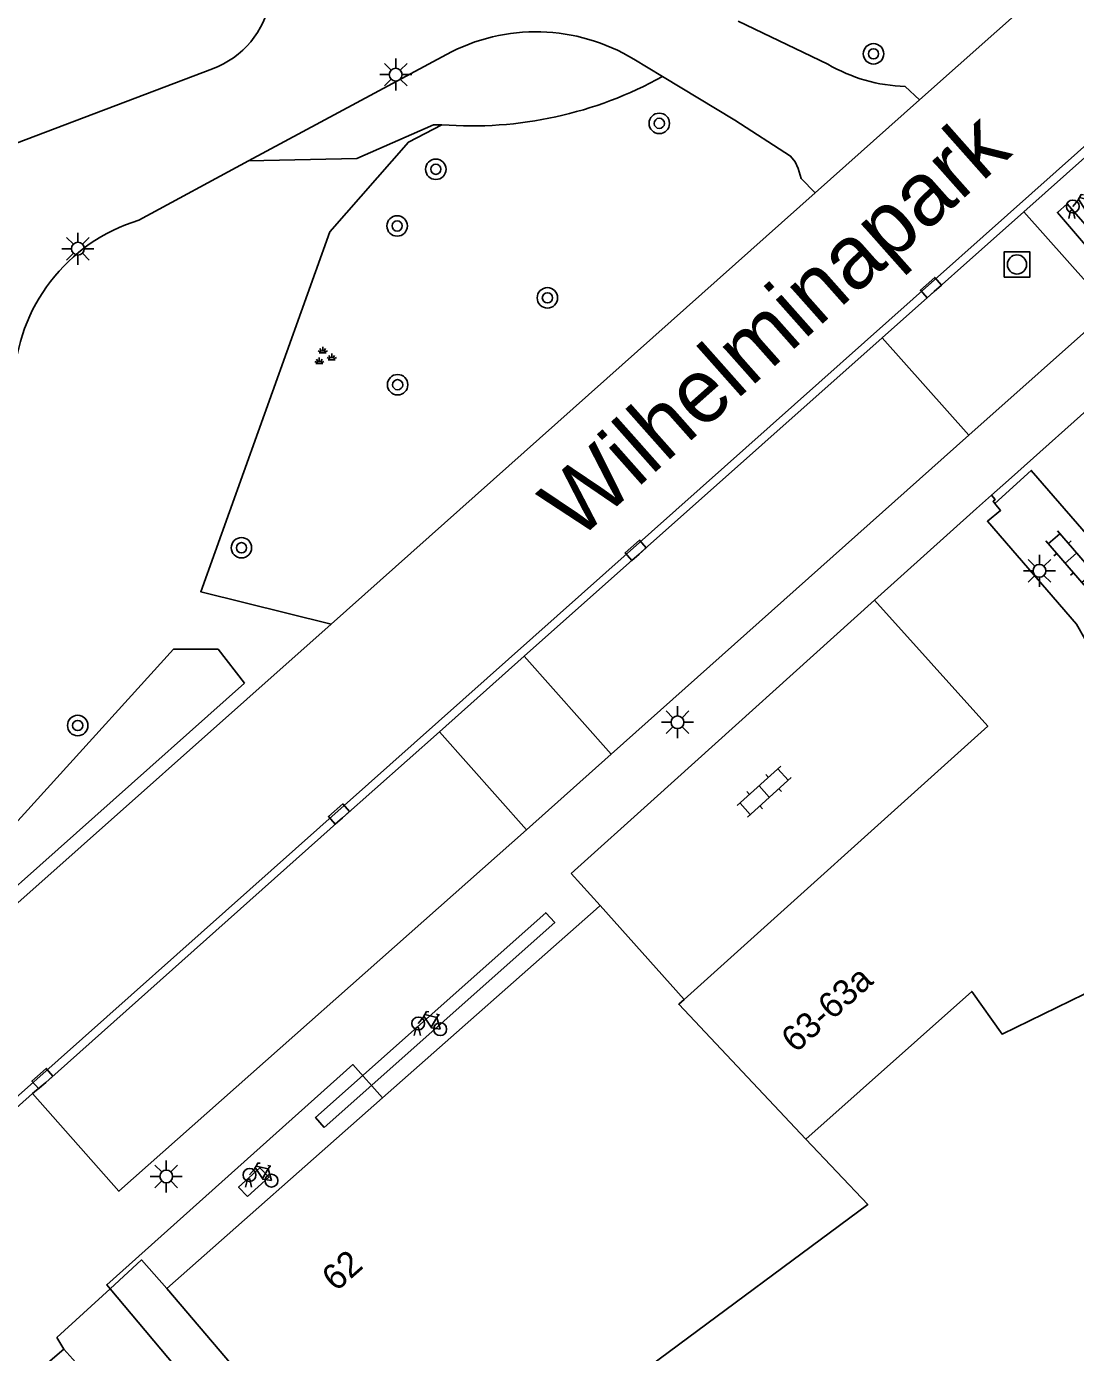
# Model space of a CAD drawing. Extents: x 132998 to 136004, y 396998 to 398512.
# Drawn here: x 133696.1 to 133737.1, y 397524.1 to 397576 of the extents above; entities that cross this region are included whole.
import ezdxf

# ---------------------------------------------------------------- set-up
doc = ezdxf.new("R2010")
doc.units = 0
for name, color, linetype in [('gg-afsc-muur', 7, 'Continuous'), ('gg-anno-huisnummerreeks BGT', 7, 'Continuous'), ('gg-anno-openbare ruimte label', 7, 'Continuous'), ('gg-bbg-gedigitaliseerde bebouwing', 7, 'Continuous'), ('gg-bbg-hoofdgebouw', 7, 'Continuous'), ('gg-bbg-onder overbouw', 7, 'Continuous'), ('gg-bbg-pand overbouw', 7, 'Continuous'), ('gg-bbg-tussenscheiding', 7, 'Continuous'), ('gg-knt-onverhard', 7, 'Continuous'), ('gg-knt-verharding', 7, 'Continuous'), ('gg-knt-verharding nz', 7, 'Continuous'), ('gt-grn-groengrens', 7, 'Continuous'), ('gt-symb-boom', 7, 'Continuous'), ('gt-symb-fietsenrek', 7, 'Continuous'), ('gt-symb-groenvak', 7, 'Continuous'), ('gt-symb-klinker verharding', 7, 'Continuous'), ('gt-symb-kolk', 7, 'Continuous'), ('gt-symb-lichtmast', 7, 'Continuous'), ('gt-symb-rioolschacht', 7, 'Continuous')]:
    doc.layers.add(name, color=color, linetype=linetype)

# ---------------------------------------------------------------- blocks, each defined once
blk = doc.blocks.new('gt0-BOOM')
at = {"layer": 'gt-symb-boom'}
for radius in [0.4, 0.2]:
    blk.add_circle((0, 0), radius, dxfattribs=at)
blk = doc.blocks.new('gt0-GRVAK')
at = {"layer": 'gt-symb-groenvak'}
for p, q in [((-0.11, 0.189), (-0.228, 0.24)), ((-0.182, 0.153), (0.088, 0.153)), ((-0.091, 0.211), (-0.156, 0.322)), ((-0.047, 0.214), (-0.047, 0.393)), ((-0.004, 0.211), (0.061, 0.322)), ((0.015, 0.189), (0.133, 0.24)), ((0.262, -0.052), (0.197, 0.059)), ((0.305, -0.049), (0.305, 0.13)), ((0.349, -0.052), (0.414, 0.059)), ((-0.245, -0.228), (-0.363, -0.177)), ((-0.318, -0.264), (-0.047, -0.264)), ((-0.226, -0.206), (-0.291, -0.095)), ((-0.183, -0.203), (-0.183, -0.024)), ((-0.139, -0.206), (-0.074, -0.095)), ((-0.12, -0.228), (-0.002, -0.177)), ((0.243, -0.074), (0.125, -0.023)), ((0.17, -0.11), (0.441, -0.11)), ((0.368, -0.074), (0.486, -0.023))]:
    blk.add_line(p, q, dxfattribs=at)
blk = doc.blocks.new('gt0-LMAST')
at = {"layer": 'gt-symb-lichtmast'}
for p, q in [((-0.005, 0.246), (-0.005, 0.621)), ((-0.182, 0.173), (-0.447, 0.438)), ((0.172, 0.173), (0.437, 0.438)), ((-0.255, -0.004), (-0.63, -0.004)), ((-0.182, -0.181), (-0.447, -0.446)), ((-0.005, -0.254), (-0.005, -0.629)), ((0.437, -0.446), (0.172, -0.181)), ((0.245, -0.004), (0.62, -0.004))]:
    blk.add_line(p, q, dxfattribs=at)
blk.add_circle((-0.005, -0.004), 0.25, dxfattribs=at)
blk = doc.blocks.new('gt0-KOLK')
at = {"layer": 'gt-symb-kolk'}
blk.add_lwpolyline([(0, 0), (0.375, 0), (0.375, 0.4), (-0.375, 0.4), (-0.375, 0), (0, 0)], dxfattribs=at)
blk = doc.blocks.new('gt0-FREK')
at = {"layer": 'gt-symb-fietsenrek'}
for p, q in [((0.259, 0.762), (0.294, 0.823)), ((0.54, 0.335), (0.259, 0.762)), ((0.294, 0.823), (0.767, 0.714)), ((0.767, 0.714), (0.54, 0.335)), ((0.757, 0.841), (0.866, 0.816)), ((0.767, 0.714), (0.84, 0.822)), ((0.895, 0.252), (0.767, 0.714))]:
    blk.add_line(p, q, dxfattribs=at)
for points in [[(0.036, 0.476), (0.228, 0.708), (0.259, 0.762)], [(0.294, 0.823), (0.36, 0.937), (0.452, 0.935)], [(-0.124, 0), (-0.047, 0.312), (0.053, 0.312), (0.12, 0)], [(0.54, 0.335), (0.555, 0.305), (0.895, 0.252)]]:
    blk.add_lwpolyline(points, dxfattribs=at)
for centre in [(0.036, 0.476), (0.895, 0.252)]:
    blk.add_circle(centre, 0.252, dxfattribs=at)
blk = doc.blocks.new('gt0-KL1')
at = {"layer": 'gt-symb-klinker verharding'}
for p, q in [((-1.15, 0.3), (1.15, 0.3)), ((-1, -0.3), (-1, 0.3)), ((-0.5, 0.3), (-0.5, 0.45)), ((0, -0.3), (0, 0.3)), ((0.5, 0.3), (0.5, 0.45)), ((1, -0.3), (1, 0.3)), ((-1.15, -0.3), (1.15, -0.3)), ((-0.5, -0.45), (-0.5, -0.3)), ((0.5, -0.45), (0.5, -0.3))]:
    blk.add_line(p, q, dxfattribs=at)
blk = doc.blocks.new('gt0-RS')
at = {"layer": 'gt-symb-rioolschacht'}
blk.add_lwpolyline([(-0.5, -0.5), (0.5, -0.5), (0.5, 0.5), (-0.5, 0.5)], close=True, dxfattribs=at)
blk.add_circle((0, 0), 0.375, dxfattribs=at)

msp = doc.modelspace()

# ---------------------------------------------------------------- linework, layer by layer
at = {"layer": 'gg-afsc-muur'}
msp.add_line((133717.37, 397542.86), (133718.498, 397541.602), dxfattribs=at)
at = {"layer": 'gg-bbg-gedigitaliseerde bebouwing'}
for points in [[(133738.202, 397537.942), (133737.985, 397538.394), (133734.235, 397536.574), (133733.046, 397538.245), (133726.551, 397532.469)], [(133726.551, 397532.469), (133728.975, 397529.901), (133720.462, 397523.588)]]:
    msp.add_lwpolyline(points, dxfattribs=at)
at = {"layer": 'gg-bbg-hoofdgebouw'}
for p, q in [((133733.23, 397557.14), (133733.818, 397557.657)), ((133733.23, 397557.14), (133729.24, 397553.56)), ((133709.982, 397534.077), (133718.344, 397541.466)), ((133718.344, 397541.466), (133718.498, 397541.602)), ((133721.79, 397537.93), (133718.498, 397541.602))]:
    msp.add_line(p, q, dxfattribs=at)
for points in [[(133733.818, 397557.657), (133733.96, 397557.491), (133733.884, 397557.426), (133733.955, 397557.339)], [(133737.471, 397552.038), (133737.153, 397552.613), (133733.66, 397556.644), (133734.178, 397557.064), (133733.955, 397557.339)], [(133729.24, 397553.56), (133733.67, 397548.63), (133721.79, 397537.93)]]:
    msp.add_lwpolyline(points, dxfattribs=at)
at = {"layer": 'gg-bbg-onder overbouw'}
msp.add_line((133701.54, 397526.616), (133709.982, 397534.077), dxfattribs=at)
msp.add_lwpolyline([(133704.584, 397520.367), (133705.866, 397521.551), (133701.54, 397526.616)], dxfattribs=at)
at = {"layer": 'gg-bbg-pand overbouw'}
msp.add_line((133704.584, 397520.367), (133699.323, 397526.61), dxfattribs=at)
msp.add_lwpolyline([(133699.323, 397526.61), (133699.191, 397526.767), (133708.818, 397535.379), (133709.982, 397534.077)], dxfattribs=at)
at = {"layer": 'gg-bbg-tussenscheiding'}
msp.add_lwpolyline([(133726.551, 397532.469), (133721.578, 397537.739), (133721.79, 397537.93)], dxfattribs=at)
at = {"layer": 'gg-knt-onverhard'}
for p, q in [((133723.911, 397576.21), (133727.413, 397574.525)), ((133704.743, 397570.74), (133712.489, 397574.91)), ((133719.827, 397574.723), (133720.949, 397574.044)), ((133700.444, 397568.426), (133704.743, 397570.74))]:
    msp.add_line(p, q, dxfattribs=at)
msp.add_lwpolyline([(133720.949, 397574.044), (133723.772, 397572.336), (133725.958, 397570.932), (133726.138, 397570.71), (133726.259, 397570.451), (133726.367, 397570.06)], dxfattribs=at)
for centre, radius, start, end in [((133715.994, 397568.397), 7.397, 58.791, 118.2894), ((133730.691, 397580.194), 6.548, 239.9601, 267.8549), ((133702.478, 397561.811), 6.92, 107.0965, 177.8335)]:
    msp.add_arc(centre, radius, start, end, dxfattribs=at)
at = {"layer": 'gg-knt-verharding'}
for p, q in [((133731.007, 397573.128), (133737.974, 397579.337)), ((133681.796, 397566.18), (133703.331, 397574.351)), ((133730.446, 397573.65), (133731.007, 397573.128)), ((133726.921, 397569.497), (133731.007, 397573.128)), ((133726.367, 397570.06), (133726.921, 397569.497)), ((133707.976, 397552.621), (133726.921, 397569.497)), ((133729.54, 397563.817), (133735.082, 397568.751)), ((133715.528, 397551.357), (133729.54, 397563.817)), ((133734.48, 397558.249), (133740.019, 397563.202)), ((133733.818, 397557.657), (133734.48, 397558.249)), ((133720.613, 397545.784), (133729.24, 397553.56)), ((133691.678, 397538.127), (133707.976, 397552.621)), ((133712.21, 397548.408), (133715.528, 397551.357)), ((133717.37, 397542.86), (133720.613, 397545.784)), ((133684.398, 397523.644), (133696.286, 397534.253)), ((133699.323, 397526.61), (133697.24, 397524.708)), ((133697.509, 397524.241), (133697.24, 397524.708)), ((133693.578, 397520.912), (133697.509, 397524.241)), ((133697.509, 397524.241), (133698.776, 397522.851))]:
    msp.add_line(p, q, dxfattribs=at)
for points in [[(133563.851, 397416.375), (133563.661, 397416.601), (133748.382, 397581.05)], [(133735.082, 397568.751), (133743.197, 397575.982), (133744.833, 397577.43)], [(133733.955, 397557.339), (133735.374, 397558.632), (133739.594, 397553.765), (133737.471, 397552.038)], [(133696.286, 397534.253), (133696.808, 397534.685), (133708.413, 397545.033), (133712.21, 397548.408)]]:
    msp.add_lwpolyline(points, dxfattribs=at)
msp.add_arc((133702.123, 397577.658), 3.521, 290.0752, 110.7531, dxfattribs=at)
at = {"layer": 'gg-knt-verharding nz'}
for p, q in [((133732.929, 397560.006), (133729.54, 397563.817)), ((133718.931, 397547.529), (133732.929, 397560.006)), ((133718.931, 397547.529), (133715.528, 397551.357)), ((133715.622, 397544.569), (133712.21, 397548.408)), ((133715.622, 397544.569), (133718.931, 397547.529))]:
    msp.add_line(p, q, dxfattribs=at)
for points in [[(133736.786, 397569.057), (133736.401, 397568.729), (133738.846, 397565.881), (133739.241, 397566.235), (133736.786, 397569.057)], [(133732.929, 397560.006), (133738.476, 397564.941), (133735.082, 397568.751)], [(133696.286, 397534.253), (133699.671, 397530.426), (133715.622, 397544.569)], [(133707.707, 397532.913), (133707.367, 397533.314), (133716.374, 397541.325), (133716.729, 397540.936), (133707.707, 397532.913)], [(133704.704, 397530.221), (133705.537, 397530.98), (133705.186, 397531.345), (133704.354, 397530.585), (133704.704, 397530.221)], [(133699.323, 397526.61), (133700.557, 397527.736), (133701.54, 397526.616)]]:
    msp.add_lwpolyline(points, dxfattribs=at)
at = {"layer": 'gt-grn-groengrens'}
for points in [[(133712.306, 397572.155), (133710.999, 397571.477), (133707.918, 397567.966), (133702.869, 397553.884), (133707.976, 397552.621)], [(133704.743, 397570.74), (133708.98, 397570.836), (133711.979, 397572.155), (133712.306, 397572.155)], [(133704.589, 397550.309), (133692.849, 397539.875), (133691.909, 397540.733), (133696.856, 397546.183), (133701.803, 397551.633), (133703.547, 397551.64), (133704.589, 397550.309)]]:
    msp.add_lwpolyline(points, dxfattribs=at)
msp.add_arc((133713.462, 397587.583), 15.471, 265.7147, 298.9425, dxfattribs=at)

# ---------------------------------------------------------------- block references
at = {"layer": 'gt-symb-boom'}
for p in [(133729.203, 397574.933), (133720.818, 397572.212), (133712.071, 397570.415), (133710.557, 397568.197), (133716.439, 397565.383), (133710.577, 397561.985), (133704.464, 397555.605), (133698.055, 397548.648)]:
    msp.add_blockref('gt0-BOOM', p, dxfattribs=at)
at = {"layer": 'gt-symb-fietsenrek'}
for p in [(133736.965, 397568.485), (133711.347, 397536.515), (133704.744, 397530.587)]:
    msp.add_blockref('gt0-FREK', p, dxfattribs=at)
at = {"layer": 'gt-symb-groenvak'}
msp.add_blockref('gt0-GRVAK', (133707.693, 397563.075), dxfattribs=at)
at = {"layer": 'gt-symb-klinker verharding'}
for p, rotation in [((133736.926, 397555.201), 130.9432621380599), ((133724.922, 397546.062), 42.04255015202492)]:
    msp.add_blockref('gt0-KL1', p, dxfattribs=dict(at, rotation=rotation))
at = {"layer": 'gt-symb-kolk'}
for p, rotation in [((133731.582, 397565.633), 41.6657068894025), ((133720.026, 397555.355), 41.66570688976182), ((133708.413, 397545.033), 41.66570688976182), ((133696.808, 397534.685), 41.665706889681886)]:
    msp.add_blockref('gt0-KOLK', p, dxfattribs=dict(at, rotation=rotation))
at = {"layer": 'gt-symb-lichtmast'}
for p in [(133710.507, 397574.123), (133698.067, 397567.311), (133735.702, 397554.706), (133721.536, 397548.781), (133701.527, 397531.007)]:
    msp.add_blockref('gt0-LMAST', p, dxfattribs=at)
at = {"layer": 'gt-symb-rioolschacht'}
msp.add_blockref('gt0-RS', (133734.816, 397566.69), dxfattribs=at)

# ---------------------------------------------------------------- texts
at = {"layer": 'gg-anno-huisnummerreeks BGT'}
for s, rotation, p in [('63-63a', 42, (133726.156, 397535.806)), ('62', 41.5, (133708.168, 397526.467))]:
    msp.add_text(s, height=1, rotation=rotation, dxfattribs=at).set_placement(p)
at = {"layer": 'gg-anno-openbare ruimte label'}
msp.add_text('Wilhelminapark', height=2.5, rotation=41.6, dxfattribs=at).set_placement((133717.595, 397555.835))

doc.saveas('drawing.dxf')
